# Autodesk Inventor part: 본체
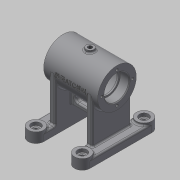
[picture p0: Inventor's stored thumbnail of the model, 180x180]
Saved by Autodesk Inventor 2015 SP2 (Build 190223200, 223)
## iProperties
Created: 2015-11
Part Number: 본체
Material: 일반
Document SubType Name: Modeling
Designer: AMC
Density: 1 g/cm^3
Appearance: 기본값
Author: AMC
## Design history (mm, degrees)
sketch "스케치1"
  geometry: C1 r 25 at (0, 0); 1 further point
  constraints: 1 centre point, 1 coincident
  dimensions: "d0" = 50 diameter of C1
extrude "돌출1" new body sketch "스케치1" stored distance "d1" = 70; taper "d2" = 0 deg
node "작업 평면1"
sketch "스케치2"
  geometry: L1 (0, -35)-(0, 35) reference; L2 (30, 40)-(30, -40); L3 (20, 40)-(20, -40); L4 (40, -40)-(40, 40); L5 (-30, 40)-(-30, -40); L6 (-20, 40)-(-20, -40); L7 (-40, -40)-(-40, 40); A1 r 10 centre (30, 40) between (40, 40) and (20, 40); A2 r 10 centre (30, -40) between (20, -40) and (40, -40); A3 r 10 centre (-30, -40) between (-40, -40) and (-20, -40); A4 r 10 centre (-30, 40) between (-20, 40) and (-40, 40); 2 further points
  constraints: 16 end point, 8 point on circle, 6 symmetric about line, 4 centre point, 4 tangent, 1 horizontal alignment, 1 midpoint, 1 parallel, 1 vertical, 2 other
  dimensions: "d7" = 40 distance from line of L4 point (0, 0); "d8" = 80 distance of L2.start L2.end; "d9" = 20 distance between parallel lines of L4 L3
extrude "돌출2" join sketch "스케치2" distance "d10" = 10; taper "d11" = 0 deg
sketch "스케치3"
  geometry: L1 (-40, 40)-(-40, -40) reference; L2 (-20, -40)-(-20, 40) reference; L3 (20, 40)-(20, -40) reference; L4 (40, -40)-(40, 40) reference; C1 r 10 at (-30, -40); A1 r 10 centre (-30, -40) between (-40, -40) and (-20, -40) reference; A2 r 10 centre (-30, 40) between (-20, 40) and (-40, 40) reference; A3 r 10 centre (30, -40) between (20, -40) and (40, -40) reference; A4 r 10 centre (30, 40) between (40, 40) and (20, 40) reference; 1 further point
  constraints: 1 centre point, 1 coincident, 1 concentric
extrude "돌출3" join sketch "스케치3" distance "d12" = 3; taper "d13" = 0 deg
sketch "스케치4"
  geometry: L1 (40, -55)-(20, -55) reference; L2 (40, -68)-(20, -68) reference; L3 (40, -68)-(40, -58) reference; L4 (20, -58)-(40, -58) reference; L5 (20, -68)-(20, -58) reference; L6 (35, -25)-(35, 25) reference; L7 (-35, 25)-(-35, -25) reference; L8 (20, -58)-(28, -58); L9 (28, -58)-(28, 0); L10 (28, 0)-(20, 0); L11 (20, 0)-(20, -58); 1 further point
  constraints: 8 end point, 2 parallel, 1 horizontal, 1 horizontal alignment, 1 perpendicular
  dimensions: "d21" = 8 distance of L10.end L9.end
extrude "돌출4" join sketch "스케치4" stored distance "d22" = 50; taper "d23" = 0 deg
node "작업 평면2"
sketch "스케치5"
  geometry: C1 r 5 at (0, 0); 1 further point
  constraints: 1 centre point, 1 coincident
  dimensions: "d25" = 10 diameter of C1
extrude "돌출5" join sketch "스케치5" stored distance "d26" = 50; taper "d27" = 0 deg
sketch "스케치6"
  geometry: L1 (56, 0)-(-56, 0) reference; L2 (35, 0)-(35, 16); L3 (35, 16)-(23, 16); L4 (23, 16)-(23, 14); L5 (23, 14)-(21, 14); L6 (21, 14)-(21, 21); L7 (21, 21)-(-21, 21); L8 (-21, 21)-(-21, 14); L9 (-21, 14)-(-23, 14); L10 (-23, 14)-(-23, 16); L11 (-23, 16)-(-35, 16); L12 (-35, 16)-(-35, 0); L13 (35, -25)-(35, 25) reference; L14 (-35, 25)-(-35, -25) reference; 2 further points
  constraints: 22 end point, 8 perpendicular, 4 collinear, 2 point on line, 2 vertical, 1 midpoint, 1 parallel, 1 vertical alignment
  dimensions: "d29" = 32 diameter of L3 L1; "d30" = 28 diameter of L5 L1; "d31" = 42 diameter of L7 L1; "d32" = 12 distance between parallel lines of L2 L4; "d33" = 42 distance between parallel lines of L8 L6; "d34" = 12 distance between parallel lines of L14 L10
revolve "회전1" sketch "스케치6" stored, may be unused: angle "d35" = 90 deg
sketch "스케치7"
  geometry: 2 further points
  constraints: 1 vertical alignment
  dimensions: "d36" = 20 distance of point (0, 0) point (0, 20)
hole "구멍1" sketch "스케치7" at (0, 20) diameter "d37" = 3.242; stored, may be unused: countersink angle "d41" = 90 deg, drill point angle "d43" = 118 deg; dims "d38" = 8, "d39" = 4, "d40" = 2, "d42" = 10
node "작업 평면4"
sketch "스케치8"
  geometry: L1 (-28, -4)-(28, -4); L2 (28, -4)-(28, 4); L3 (28, 4)-(-28, 4); L4 (-28, 4)-(-28, -4); L5 (-28, -4)-(28, 4); L6 (28, -4)-(-28, 4); L7 (-28, -25)-(-28, 25) reference; L8 (28, 25)-(28, -25) reference; 1 further point
  constraints: 12 end point, 2 midpoint, 2 parallel, 1 collinear, 1 horizontal, 1 perpendicular
  dimensions: "d48" = 8 distance between parallel lines of L1 L3
extrude "돌출6" join sketch "스케치8" stored distance "d49" = 50; taper "d50" = 0 deg
sketch "스케치9"
  geometry: L1 (8.5, 10)-(31.5, 10); L2 (8.5, 6.5)-(31.5, 6.5); L3 (31.5, 13.5)-(8.5, 13.5); L4 (60, -23)-(40, -23) reference; A1 r 3.5 centre (8.5, 10) between (8.5, 13.5) and (8.5, 6.5); A2 r 3.5 centre (31.5, 10) between (31.5, 6.5) and (31.5, 13.5); 2 further points
  constraints: 8 end point, 4 point on circle, 4 tangent, 2 centre point, 1 horizontal, 1 midpoint, 1 parallel, 1 vertical alignment
  dimensions: "d51" = 33 distance from line of L4 point (20, 10); "d52" = 23 distance of L1.start L1.end; "d56" = 7 distance between parallel lines of L2 L3
extrude "돌출7" cut sketch "스케치9" stored distance "d57" = 50; taper "d58" = 0 deg
hole "구멍2" diameter "d61" = 5.188; stored, may be unused: countersink angle "d65" = 90 deg, drill point angle "d67" = 118 deg; dims "d59" = 10, "d60" = 10, "d62" = 12, "d63" = 4, "d64" = 2, "d66" = 16
sketch "스케치10"
  geometry: L1 (0, -87.2)-(0, 47.2) reference; L2 (0, 0)-(-14, -24.249)
  constraints: 2 end point
  dimensions: "d70" = 28 distance of L2.start L2.end; "d73" = 30 deg angle of L1 L2
node "작업 평면6"
sketch "스케치11"
  geometry: C1 r 6 at (0, 0); 1 further point
  constraints: 1 centre point, 1 coincident
  dimensions: "d74" = 12 diameter of C1
extrude "돌출8" join sketch "스케치11" stored distance "d75" = 50; taper "d76" = 0 deg
hole "구멍3" diameter "d79" = 5.188; stored, may be unused: countersink angle "d83" = 90 deg, drill point angle "d85" = 118 deg; dims "d77" = 10, "d78" = 10, "d80" = 12, "d81" = 4, "d82" = 2, "d84" = 16
sketch "스케치12"
  geometry: L1 (-21.03, 3.044)-(21.03, 3.044); L2 (21.03, 3.044)-(21.03, -3.044); L3 (21.03, -3.044)-(-21.03, -3.044); L4 (-21.03, -3.044)-(-21.03, 3.044); L5 (0, 3.044)-(0, -3.044); L6 (-21.03, 0)-(21.03, 0); L7 (-20, -68)-(-40, -68) reference; L8 (35, 25)-(-35, 25) reference; L9 (-35, 25)-(-35, -25) reference; 1 further point
  constraints: 4 end point, 4 midpoint, 2 other
  dimensions: "d86" = 42.05917 distance between parallel lines of L2 L4; "d87" = 6.08806 distance between parallel lines of L3 L1; "d89" = 25 distance between parallel lines of L8 L6 (derived); "d90" = 35 distance between parallel lines of L5 L9 (derived)
feature "엠보싱1" sketch "스케치12" dims "d91" = 0.5, "d92" = 0
fillet "모깎기1" dims "d93" = 2
hole "구멍4" diameter "d96" = 6; stored, may be unused: countersink angle "d100" = 90 deg, drill point angle "d102" = 118 deg; dims "d94" = 10, "d95" = 10, "d97" = 12, "d98" = 12, "d99" = 4, "d101" = 16
chamfer "모따기1" distance "d109" = 1; stored, may be unused: second distance "d110" = 2, angle "d111" = 45 deg
fillet "모깎기2" dims "d112" = 0.3
fillet "모깎기3" dims "d113" = 3
node "솔리드1"
pattern_linear "직사각형 패턴1" dims "d16" = 80
mirror "대칭1"
pattern_circular "원형 패턴1" dims angle "d45" = 360 deg
mirror "대칭2"
pattern_linear "직사각형 패턴2" dims "d105" = 80
node "투영된 루프1"
node "투영된 루프2"
node "투영된 루프3"
node "투영된 루프4"
other parameters: "d3" = -68, "d24" = 28, "d47" = -45
